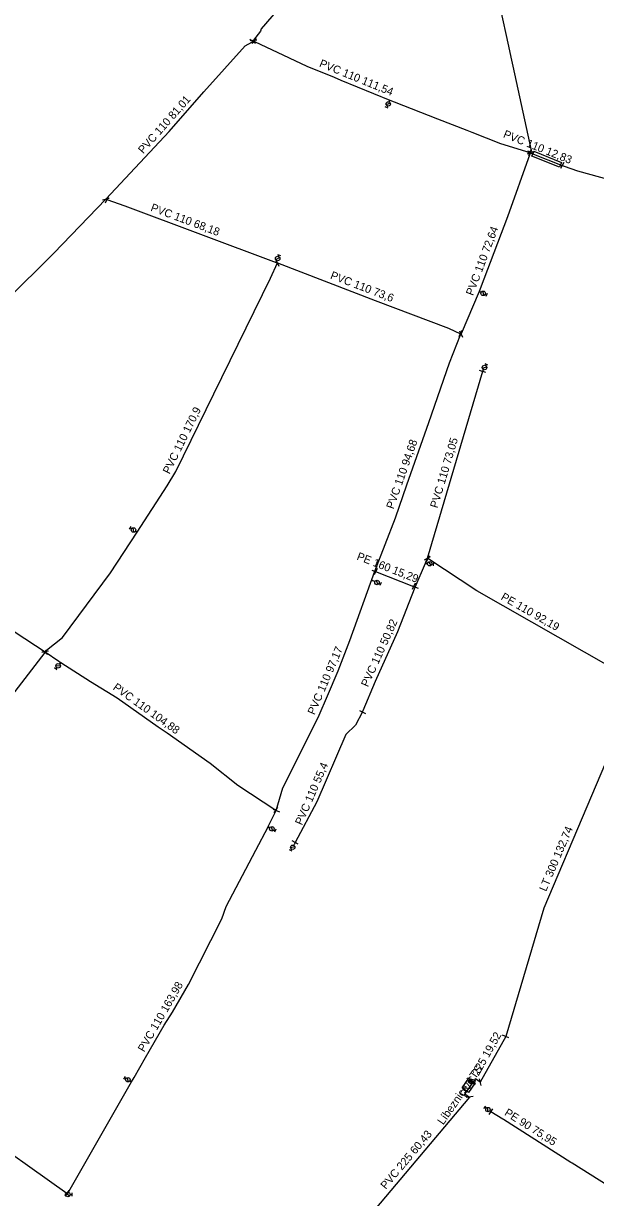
# Model space of a CAD drawing. Extents: x -736619 to -735426, y -1033122 to -1031044.
# Drawn here: x -736292.8 to -736078.3, y -1032731.9 to -1032291.7 of the extents above; entities that cross this region are included whole.
import ezdxf

# ---------------------------------------------------------------- set-up
doc = ezdxf.new("R2010")
doc.units = 0
for name, color, linetype in [('Vrstva 1', 7, 'Continuous'), ('Vrstva 17', 7, 'Continuous'), ('Vrstva 25', 7, 'Continuous'), ('Vrstva 26', 7, 'Continuous'), ('Vrstva 27', 7, 'Continuous'), ('Vrstva 29', 7, 'Continuous'), ('Vrstva 63', 7, 'Continuous')]:
    doc.layers.add(name, color=color, linetype=linetype)

# ---------------------------------------------------------------- blocks, each defined once
blk = doc.blocks.new('100')
at = {"layer": 'Vrstva 1'}
blk.add_circle((0, 0), 0.127, dxfattribs=at)
blk = doc.blocks.new('133')
at = {"layer": 'Vrstva 1'}
for p, q in [((0.28, 0), (0, 0)), ((0.54, 0.58), (1.7, -0.58)), ((1.94, 0), (2.52, 0)), ((2.52, 0.58), (2.52, -0.58))]:
    blk.add_line(p, q, dxfattribs=at)
blk.add_circle((1.105, 0.003), 0.825, dxfattribs=at)
blk = doc.blocks.new('147')
at = {"layer": 'Vrstva 1'}
blk.add_line((0, 1.27), (0, -1.27), dxfattribs=at)

msp = doc.modelspace()

# ---------------------------------------------------------------- linework, layer by layer
at = {"layer": 'Vrstva 17'}
for p, q in [((-736206.885, -1032298.385), (-736206.59, -1032298)), ((-736206.59, -1032298), (-736206.255, -1032298.28)), ((-736102.602, -1032339.755), (-736102.73, -1032340.21)), ((-736102.73, -1032340.21), (-736102.969, -1032340.135)), ((-736102.761, -1032340.294), (-736102.73, -1032340.21)), ((-736261.91, -1032357.61), (-736261.53, -1032357.74)), ((-736128.968, -1032408.007), (-736128.74, -1032408.11)), ((-736120.666, -1032422.233), (-736141.438, -1032492.269)), ((-736141.438, -1032492.269), (-736141.171, -1032492.334)), ((-736160.794, -1032497.179), (-736161.034, -1032497.093)), ((-736160.794, -1032497.179), (-736146.557, -1032502.743)), ((-736146.557, -1032502.743), (-736145.939, -1032503)), ((-736284.67, -1032527.33), (-736284.824, -1032527.529)), ((-736198.248, -1032586.636), (-736198.03, -1032586.78)), ((-736112.001, -1032671.548), (-736121.533, -1032688.581)), ((-736125.507, -1032694.196), (-736164.447, -1032740.408))]:
    msp.add_line(p, q, dxfattribs=at)
for points in [[(-736137.3, -1032232.9), (-736140.14, -1032232.68), (-736144.151, -1032235.36), (-736156.63, -1032243.7), (-736158.824, -1032245.508), (-736168.758, -1032253.69), (-736171.21, -1032255.71), (-736180.129, -1032266.149), (-736194.07, -1032282.467), (-736203.71, -1032293.75), (-736203.95, -1032294.59), (-736206.59, -1032298)], [(-736127.76, -1032231.89), (-736123.892, -1032245.969), (-736122.336, -1032251.633), (-736121.23, -1032255.66), (-736121.14, -1032256.039), (-736117.633, -1032270.788), (-736117.472, -1032271.47), (-736114.01, -1032286.03), (-736110.957, -1032300.183), (-736110.434, -1032302.61), (-736109.829, -1032305.414), (-736109.344, -1032307.663), (-736102.5, -1032339.39), (-736102.602, -1032339.755)], [(-736261.91, -1032357.61), (-736238.22, -1032332.17), (-736225.16, -1032317.32), (-736209.71, -1032300.13), (-736207.18, -1032298.77), (-736206.885, -1032298.385)], [(-736206.255, -1032298.28), (-736205.92, -1032298.56), (-736199.81, -1032301.452), (-736186.61, -1032307.7), (-736176.342, -1032311.882), (-736173.828, -1032312.907), (-736155.43, -1032320.4), (-736153.824, -1032321.031), (-736137.508, -1032327.441), (-736126.578, -1032331.735), (-736124.654, -1032332.491), (-736113.94, -1032336.7), (-736102.969, -1032340.135)], [(-736102.761, -1032340.294), (-736102.92, -1032340.73), (-736111.37, -1032364.15), (-736120.15, -1032387.62), (-736121.91, -1032392.19), (-736128.74, -1032408.11)], [(-736102.73, -1032340.21), (-736102.163, -1032340.436), (-736090.814, -1032344.963)], [(-736090.814, -1032344.963), (-736090.12, -1032345.24), (-736085.05, -1032346.96), (-736072.79, -1032350.32), (-736070.508, -1032351.05), (-736052.156, -1032356.918), (-736039.257, -1032361.042), (-736038.655, -1032361.234), (-736018.763, -1032367.594), (-735990.126, -1032376.75), (-735978.99, -1032380.31), (-735977.1, -1032381.05)], [(-736261.91, -1032357.61), (-736281.44, -1032377.85), (-736299.4, -1032395.69), (-736313.59, -1032410.41), (-736317.07, -1032414.11), (-736332.24, -1032430.24), (-736359.63, -1032459.8), (-736369.87, -1032470.64)], [(-736261.53, -1032357.74), (-736254.79, -1032360.07), (-736198.07, -1032381.33), (-736197.62, -1032381.49)], [(-736284.67, -1032527.33), (-736284.21, -1032526.63), (-736278.17, -1032521.95), (-736260.2, -1032497.66), (-736250.23, -1032482.48), (-736238.94, -1032465.04), (-736235.7, -1032459.64), (-736221.45, -1032430.5), (-736200.17, -1032387.25), (-736197.62, -1032381.49)], [(-736197.62, -1032381.49), (-736160.91, -1032395.54), (-736133.43, -1032405.99), (-736128.968, -1032408.007)], [(-736161.034, -1032497.093), (-736153.35, -1032477.07), (-736149.12, -1032464.71), (-736140.88, -1032441.3), (-736133.03, -1032418.99), (-736128.93, -1032408.49), (-736128.74, -1032408.11)], [(-736369.665, -1032470.784), (-736352.83, -1032482.62), (-736345.1, -1032487.61), (-736332.9, -1032495.32), (-736315.17, -1032506.58), (-736310.03, -1032510.36), (-736295.95, -1032519.89), (-736284.67, -1032527.33)], [(-736145.939, -1032503), (-736142.101, -1032494.019), (-736141.438, -1032492.269)], [(-736061.794, -1032539.148), (-736122.796, -1032504.389), (-736141.171, -1032492.334)], [(-736198.03, -1032586.78), (-736195.53, -1032578.31), (-736186.94, -1032561.21), (-736181.95, -1032551.02), (-736178.83, -1032543.84), (-736174.8, -1032534.41), (-736170.45, -1032523.02), (-736161.034, -1032497.093)], [(-736165.679, -1032549.815), (-736165.427, -1032549.293), (-736160.829, -1032538.299), (-736152.412, -1032519.664), (-736145.939, -1032503)], [(-736284.824, -1032527.529), (-736303.72, -1032551.93), (-736310.34, -1032561.33), (-736317.93, -1032570.73)], [(-736284.67, -1032527.33), (-736279.54, -1032530.73), (-736278.82, -1032531.31), (-736267.71, -1032538.44), (-736257.67, -1032544.53), (-736242.36, -1032555.47), (-736239.01, -1032557.6), (-736222.77, -1032569.04), (-736212.43, -1032577.24), (-736198.248, -1032586.636)], [(-736165.679, -1032549.815), (-736168.346, -1032554.797), (-736171.912, -1032558.304), (-736182.781, -1032583.54), (-736190.901, -1032598.786)], [(-736065.393, -1032547.472), (-736097.661, -1032623.347), (-736112.001, -1032671.548)], [(-736485.543, -1032588.693), (-736471.99, -1032599.23), (-736424.93, -1032629.8), (-736408.64, -1032640.35), (-736381.3, -1032659.56), (-736311.84, -1032705.2), (-736276.525, -1032730.304)], [(-736276.525, -1032730.304), (-736276.32, -1032730.45), (-736252.3, -1032688.52), (-736251.36, -1032686.87), (-736247.11, -1032679.43), (-736240.09, -1032667.3), (-736236.96, -1032662.35), (-736230.99, -1032651.98), (-736218.44, -1032627.4), (-736216.79, -1032622.75), (-736205.75, -1032601.71), (-736201.1, -1032592.87), (-736201.028, -1032592.727), (-736198.03, -1032586.78)], [(-736121.533, -1032688.581), (-736123.379, -1032687.338), (-736124.118, -1032688.387), (-736124.502, -1032688.933)], [(-736124.502, -1032688.933), (-736127.34, -1032692.961), (-736125.507, -1032694.196)], [(-736053.341, -1032740.177), (-736060.689, -1032735.583), (-736061.081, -1032735.355), (-736087.044, -1032719.018), (-736087.511, -1032718.722), (-736112.832, -1032702.648), (-736113.092, -1032702.546), (-736117.604, -1032699.702)]]:
    msp.add_lwpolyline(points, dxfattribs=at)
at = {"layer": 'Vrstva 25'}
msp.add_lwpolyline([(-736124.2, -1032688.33), (-736124.94, -1032689.41), (-736126.01, -1032688.66), (-736125.27, -1032687.59), (-736124.2, -1032688.33)], dxfattribs=at)
at = {"layer": 'Vrstva 26'}
msp.add_lwpolyline([(-736125.81, -1032687.16), (-736123.437, -1032688.827), (-736125.989, -1032692.46), (-736128.36, -1032690.79), (-736125.81, -1032687.16)], dxfattribs=at)
at = {"layer": 'Vrstva 27'}
msp.add_lwpolyline([(-736101.495, -1032339.626), (-736091.086, -1032343.778), (-736091.827, -1032345.636), (-736102.236, -1032341.483), (-736101.495, -1032339.626)], dxfattribs=at)
at = {"layer": 'Vrstva 63'}
for p, q in [((-736155.43, -1032320.4), (-736155.619, -1032320.863)), ((-736198.07, -1032381.33), (-736197.895, -1032380.862)), ((-736121.91, -1032392.19), (-736121.451, -1032392.388)), ((-736250.23, -1032482.48), (-736250.648, -1032482.206)), ((-736162.257, -1032500.461), (-736161.28, -1032500.807)), ((-736278.82, -1032531.31), (-736279.134, -1032531.699)), ((-736201.1, -1032592.87), (-736200.657, -1032593.103)), ((-736190.901, -1032598.786), (-736191.337, -1032599.598)), ((-736252.3, -1032688.52), (-736252.734, -1032688.272)), ((-736117.604, -1032699.702), (-736117.793, -1032699.559))]:
    msp.add_line(p, q, dxfattribs=at)
for points in [[(-736120.666, -1032422.233), (-736120.59, -1032421.975), (-736120.431, -1032421.667)], [(-736142.101, -1032494.019), (-736141.844, -1032494.112), (-736141.601, -1032494.132)], [(-736276.319, -1032730.448), (-736276.524, -1032730.737), (-736277.274, -1032730.737)]]:
    msp.add_lwpolyline(points, dxfattribs=at)

# ---------------------------------------------------------------- block references
at = {"layer": 'Vrstva 25'}
for p, xscale, yscale, rotation in [((-736155.619, -1032320.863), 0.9999999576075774, 0.9999999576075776, -113.00000088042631), ((-736197.895, -1032380.862), 0.9999999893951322, 0.9999999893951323, 70.00000094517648), ((-736121.451, -1032392.388), 1.0198568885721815, 1.0198568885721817, -26.39398240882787), ((-736120.431, -1032421.667), 0.999999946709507, 0.999999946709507, 62.999999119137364), ((-736250.648, -1032482.206), 0.9999999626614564, 0.9999999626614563, 147.0000015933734), ((-736141.601, -1032494.132), 1.0011216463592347, 1.0011216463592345, -6.5826102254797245), ((-736161.28, -1032500.807), 1.0275072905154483, 1.027507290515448, -24.689105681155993), ((-736279.134, -1032531.699), 0.9999999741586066, 0.9999999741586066, -129.99999870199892), ((-736200.657, -1032593.103), 1.0037041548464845, 1.0037041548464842, -29.379208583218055), ((-736191.337, -1032599.598), 0.999999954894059, 0.9999999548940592, -119.00000058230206), ((-736252.734, -1032688.272), 0.9999999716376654, 0.9999999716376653, 150.00000103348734), ((-736117.793, -1032699.559), 0.9999999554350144, 0.9999999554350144, 143.00000079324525)]:
    msp.add_blockref('133', p, dxfattribs=dict(at, xscale=xscale, yscale=yscale, rotation=rotation))
msp.add_blockref('133', (-736277.274, -1032730.737), dxfattribs=at)
at = {"layer": 'Vrstva 29'}
for p, xscale, yscale, rotation in [((-736206.885, -1032298.385), 0.9999999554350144, 0.9999999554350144, 53.00000079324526), ((-736206.59, -1032298), 1.0011216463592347, 1.0011216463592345, 96.58261022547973), ((-736206.255, -1032298.28), 0.9999999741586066, 0.9999999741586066, 140.00000129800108), ((-736102.73, -1032340.21), 0.9999999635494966, 0.9999999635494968, -65.00000039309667), ((-736102.602, -1032339.755), 0.9999999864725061, 0.9999999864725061, 74.0000013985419), ((-736102.969, -1032340.135), 1.0335064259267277, 1.033506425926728, -23.04128150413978), ((-736102.761, -1032340.294), 0.9999999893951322, 0.9999999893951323, 70.00000094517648), ((-736090.814, -1032344.963), 1.022584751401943, 1.022584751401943, -25.818974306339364), ((-736261.91, -1032357.61), 0.9999999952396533, 0.9999999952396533, -77.00000056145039), ((-736261.53, -1032357.74), 1.0316957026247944, 1.0316957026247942, 156.4154111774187), ((-736197.62, -1032381.49), 1.022584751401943, 1.022584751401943, 25.818974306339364), ((-736128.968, -1032408.007), 1.0169561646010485, 1.0169561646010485, -26.97601647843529), ((-736128.74, -1032408.11), 1.0275072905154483, 1.027507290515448, 24.689105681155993), ((-736120.666, -1032422.233), 0.9999999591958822, 0.9999999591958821, -107.99999945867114), ((-736141.438, -1032492.269), 0.999999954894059, 0.9999999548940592, -60.999999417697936), ((-736141.171, -1032492.334), 1.022584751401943, 1.022584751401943, 154.18102569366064), ((-736161.034, -1032497.093), 0.9999999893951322, 0.9999999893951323, 70.00000094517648), ((-736160.794, -1032497.179), 1.0275072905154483, 1.027507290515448, -24.689105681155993), ((-736146.557, -1032502.743), 1.022584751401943, 1.022584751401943, -25.818974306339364), ((-736145.939, -1032503), 0.9999999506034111, 0.9999999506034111, 67.99999971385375), ((-736284.67, -1032527.33), 0.9999999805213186, 0.9999999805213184, -79.00000058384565), ((-736284.824, -1032527.529), 0.9999999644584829, 0.999999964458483, -129.00000106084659), ((-736165.679, -1032549.815), 0.999999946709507, 0.999999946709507, 62.999999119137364), ((-736198.248, -1032586.636), 0.9999999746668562, 0.999999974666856, -34.00000045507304), ((-736198.03, -1032586.78), 0.9999999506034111, 0.9999999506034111, 67.99999971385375), ((-736190.901, -1032598.786), 0.999999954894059, 0.9999999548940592, -119.00000058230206), ((-736112.001, -1032671.548), 0.9999999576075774, 0.9999999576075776, -113.00000088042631), ((-736121.533, -1032688.581), 1.0045862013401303, 1.00458620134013, -166.82590933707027), ((-736124.502, -1032688.933), 0.9999999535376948, 0.9999999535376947, -126.00000134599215), ((-736125.507, -1032694.196), 1.000191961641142, 1.000191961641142, -82.91099886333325), ((-736117.604, -1032699.702), 0.9999999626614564, 0.9999999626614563, -32.99999840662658), ((-736276.525, -1032730.304), 0.9999999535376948, 0.9999999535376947, -36.000001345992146)]:
    msp.add_blockref('147', p, dxfattribs=dict(at, xscale=xscale, yscale=yscale, rotation=rotation))
at = {"layer": 'Vrstva 63'}
for p, xscale, yscale, rotation in [((-736155.524, -1032320.632), 0.9999999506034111, 0.9999999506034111, 67.99999971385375), ((-736197.982, -1032381.096), 0.9999999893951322, 0.9999999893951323, 70.00000094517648), ((-736121.711, -1032392.276), 1.0198568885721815, 1.0198568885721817, -26.39398240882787), ((-736120.59, -1032421.975), 0.9999999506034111, 0.9999999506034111, 67.99999971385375), ((-736250.439, -1032482.343), 0.9999999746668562, 0.999999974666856, -34.00000045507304), ((-736141.844, -1032494.112), 1.0028916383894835, 1.0028916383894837, -13.697207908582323), ((-736162.017, -1032500.546), 1.0275072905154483, 1.027507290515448, -24.689105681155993), ((-736278.977, -1032531.504), 0.9999999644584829, 0.999999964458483, 50.999998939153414), ((-736201.046, -1032592.898), 1.0037041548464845, 1.0037041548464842, -29.379208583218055), ((-736252.517, -1032688.396), 0.9999999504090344, 0.9999999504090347, -31.000001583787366), ((-736276.465, -1032730.654), 0.9999999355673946, 0.9999999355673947, 55.0000006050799)]:
    msp.add_blockref('100', p, dxfattribs=dict(at, xscale=xscale, yscale=yscale, rotation=rotation))

# ---------------------------------------------------------------- texts
for s, rotation, p in [('PVC 110 111,54', 337.84, (-736182.142, -1032307.793)), ('PVC 110 81,01', 48.67, (-736247.918, -1032340.766)), ('PVC 110 12,83', 338.25, (-736113.155, -1032334.327)), ('PVC 110 68,18', 339.45, (-736245.4, -1032361.879)), ('PVC 110 72,64', 69.49, (-736124.233, -1032393.971)), ('PVC 110 73,6', 339.06, (-736178.009, -1032387.282)), ('PVC 110 170,9', 63.94, (-736238.084, -1032460.874)), ('PVC 110 94,68', 70.61, (-736154.078, -1032473.98)), ('PVC 110 73,05', 73.48, (-736137.576, -1032473.621)), ('PE 160 15,29', 338.65, (-736168.084, -1032492.61)), ('PE 110 92,19', 330.33, (-736114.051, -1032507.532)), ('PVC 110 50,82', 65.69, (-736163.667, -1032540.694)), ('PVC 110 97,17', 66.86, (-736183.691, -1032551.144)), ('PVC 110 104,88', 324.45, (-736259.552, -1032541.218)), ('PVC 110 55,4', 66.7, (-736188.388, -1032592.517)), ('LT 300 132,74', 66.96, (-736096.846, -1032617.342)), ('PVC 110 163,98', 60.07, (-736247.563, -1032677.562)), ('PVC 225 19,52', 60.77, (-736126.758, -1032694.643)), ('Líbeznice ATS', 54.91, (-736135.428, -1032704.852)), ('PE 90 75,95', 327.59, (-736112.736, -1032700.812)), ('PVC 225 60,43', 49.88, (-736156.95, -1032729.028))]:
    msp.add_text(s, height=2.99999, rotation=rotation, dxfattribs=at).set_placement(p)

doc.saveas('drawing.dxf')
